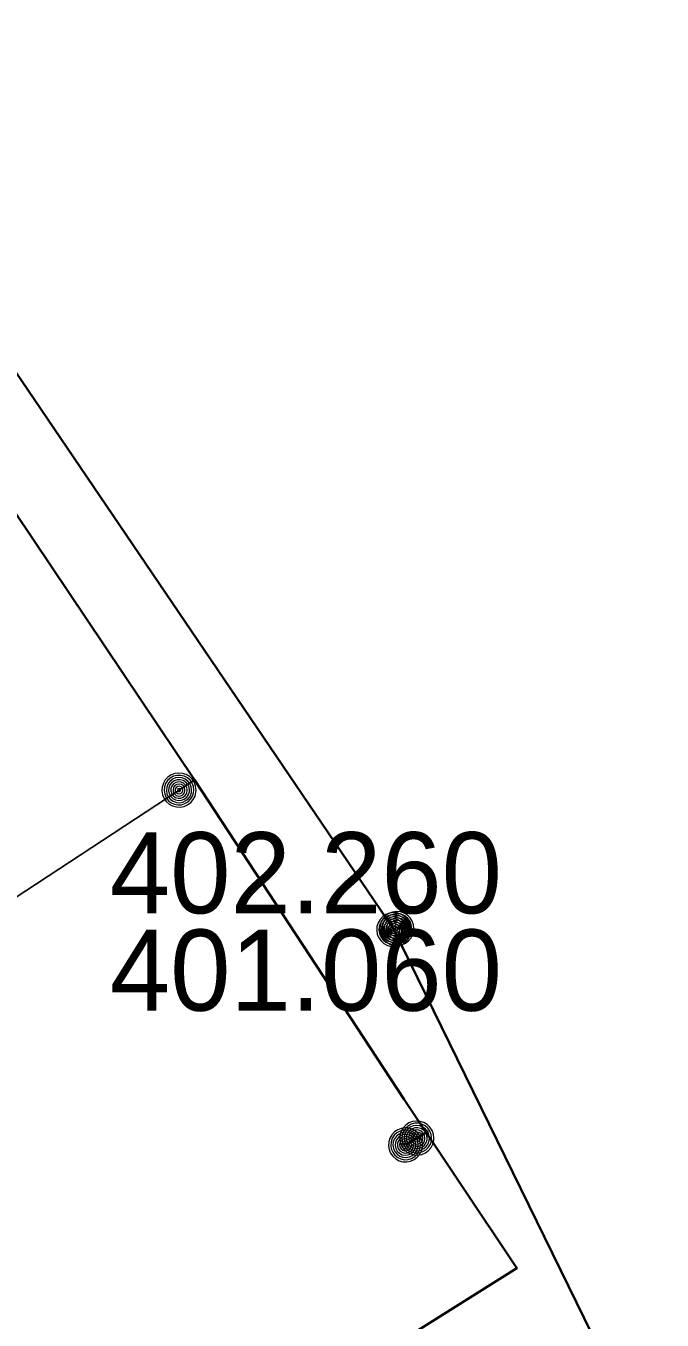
# Model space of a CAD drawing. Extents: x -873619 to -867639, y -1015082 to -1012326.
# Drawn here: x -867894.84 to -867886.21, y -1012917.41 to -1012899.86 of the extents above; entities that cross this region are included whole.
import ezdxf

# ---------------------------------------------------------------- set-up
doc = ezdxf.new("R2010")
doc.units = 0
doc.header["$LTSCALE"] = 0.44
for name, color, linetype, lineweight in [('1', 7, 'Continuous', 13), ('12', 7, 'Continuous', 13), ('21', 7, 'Continuous', 35), ('25', 7, 'Continuous', 13), ('3', 7, 'Continuous', 25), ('32', 7, 'Continuous', 13), ('8', 7, 'Continuous', 13)]:
    doc.layers.add(name, color=color, linetype=linetype, lineweight=lineweight)

msp = doc.modelspace()

# ---------------------------------------------------------------- linework, layer by layer
at = {"layer": '1', "lineweight": 35}
msp.add_line((-867889.689, -1012915.029), (-867889.411, -1012914.86), dxfattribs=at)
msp.add_lwpolyline([(-867979.181, -1012799.683), (-867972.83, -1012801.89), (-867965.59, -1012804.78), (-867963.787, -1012807.409), (-867948.768, -1012827.087), (-867948.538, -1012827.407), (-867943.513, -1012834.828), (-867938.476, -1012842.701), (-867934.013, -1012848.778), (-867931.689, -1012852.506), (-867924.702, -1012862.569), (-867923.496, -1012864.901), (-867916.531, -1012874.592), (-867908.231, -1012887.091), (-867905.717, -1012890.99), (-867899.122, -1012900.29), (-867892.55, -1012910.082), (-867889.71, -1012914.412), (-867888.18, -1012916.7), (-867891.84, -1012919), (-867886.89, -1012927.31), (-867886.728, -1012931.158)], dxfattribs=at)
at = {"layer": '12'}
for points in [[(-867892.53, -1012910.219), (-867892.536, -1012910.167), (-867892.553, -1012910.117), (-867892.582, -1012910.073), (-867892.619, -1012910.036), (-867892.664, -1012910.009), (-867892.714, -1012909.992), (-867892.767, -1012909.988), (-867892.819, -1012909.995), (-867892.868, -1012910.014), (-867892.911, -1012910.043), (-867892.947, -1012910.082), (-867892.973, -1012910.127), (-867892.989, -1012910.178), (-867892.992, -1012910.23), (-867892.984, -1012910.282), (-867892.964, -1012910.331), (-867892.933, -1012910.374), (-867892.894, -1012910.408), (-867892.848, -1012910.434), (-867892.797, -1012910.448), (-867892.744, -1012910.45), (-867892.693, -1012910.44), (-867892.645, -1012910.419), (-867892.602, -1012910.388), (-867892.568, -1012910.347), (-867892.544, -1012910.301), (-867892.532, -1012910.25)], [(-867892.56, -1012910.219), (-867892.566, -1012910.17), (-867892.583, -1012910.124), (-867892.611, -1012910.084), (-867892.648, -1012910.052), (-867892.692, -1012910.03), (-867892.74, -1012910.019), (-867892.789, -1012910.019), (-867892.836, -1012910.032), (-867892.879, -1012910.056), (-867892.915, -1012910.089), (-867892.942, -1012910.13), (-867892.958, -1012910.177), (-867892.962, -1012910.226), (-867892.955, -1012910.274), (-867892.936, -1012910.319), (-867892.906, -1012910.359), (-867892.868, -1012910.39), (-867892.824, -1012910.41), (-867892.776, -1012910.42), (-867892.727, -1012910.418), (-867892.68, -1012910.403), (-867892.637, -1012910.378), (-867892.603, -1012910.344), (-867892.577, -1012910.302), (-867892.563, -1012910.255)], [(-867892.59, -1012910.219), (-867892.596, -1012910.174), (-867892.613, -1012910.132), (-867892.641, -1012910.097), (-867892.677, -1012910.07), (-867892.719, -1012910.053), (-867892.764, -1012910.048), (-867892.809, -1012910.054), (-867892.85, -1012910.073), (-867892.885, -1012910.101), (-867892.912, -1012910.138), (-867892.928, -1012910.18), (-867892.932, -1012910.225), (-867892.925, -1012910.27), (-867892.906, -1012910.311), (-867892.877, -1012910.345), (-867892.84, -1012910.371), (-867892.797, -1012910.387), (-867892.752, -1012910.39), (-867892.707, -1012910.382), (-867892.667, -1012910.362), (-867892.633, -1012910.333), (-867892.607, -1012910.295), (-867892.593, -1012910.252)], [(-867892.62, -1012910.219), (-867892.625, -1012910.178), (-867892.643, -1012910.141), (-867892.67, -1012910.11), (-867892.705, -1012910.089), (-867892.745, -1012910.078), (-867892.786, -1012910.08), (-867892.825, -1012910.093), (-867892.859, -1012910.117), (-867892.884, -1012910.149), (-867892.899, -1012910.187), (-867892.902, -1012910.228), (-867892.894, -1012910.268), (-867892.874, -1012910.304), (-867892.845, -1012910.333), (-867892.808, -1012910.352), (-867892.768, -1012910.36), (-867892.727, -1012910.356), (-867892.689, -1012910.341), (-867892.657, -1012910.315), (-867892.634, -1012910.281), (-867892.621, -1012910.242)], [(-867892.65, -1012910.219), (-867892.655, -1012910.183), (-867892.673, -1012910.151), (-867892.699, -1012910.126), (-867892.733, -1012910.111), (-867892.769, -1012910.108), (-867892.804, -1012910.116), (-867892.835, -1012910.136), (-867892.858, -1012910.164), (-867892.871, -1012910.198), (-867892.871, -1012910.235), (-867892.86, -1012910.27), (-867892.839, -1012910.299), (-867892.809, -1012910.32), (-867892.774, -1012910.33), (-867892.737, -1012910.328), (-867892.703, -1012910.314), (-867892.676, -1012910.291), (-867892.657, -1012910.259), (-867892.65, -1012910.224)], [(-867892.68, -1012910.219), (-867892.685, -1012910.188), (-867892.702, -1012910.162), (-867892.728, -1012910.145), (-867892.758, -1012910.138), (-867892.789, -1012910.142), (-867892.816, -1012910.159), (-867892.834, -1012910.183), (-867892.842, -1012910.214), (-867892.838, -1012910.244), (-867892.823, -1012910.272), (-867892.799, -1012910.291), (-867892.769, -1012910.3), (-867892.738, -1012910.297), (-867892.71, -1012910.283), (-867892.69, -1012910.259), (-867892.68, -1012910.23)], [(-867892.71, -1012910.219), (-867892.715, -1012910.195), (-867892.732, -1012910.177), (-867892.755, -1012910.168), (-867892.779, -1012910.171), (-867892.8, -1012910.185), (-867892.811, -1012910.207), (-867892.811, -1012910.232), (-867892.799, -1012910.253), (-867892.779, -1012910.267), (-867892.754, -1012910.27), (-867892.731, -1012910.261), (-867892.715, -1012910.243)], [(-867892.74, -1012910.219), (-867892.745, -1012910.204), (-867892.76, -1012910.198), (-867892.775, -1012910.202), (-867892.782, -1012910.216), (-867892.778, -1012910.231), (-867892.765, -1012910.24), (-867892.75, -1012910.237), (-867892.74, -1012910.225)], [(-867889.306, -1012914.937), (-867889.312, -1012914.885), (-867889.329, -1012914.835), (-867889.358, -1012914.791), (-867889.395, -1012914.754), (-867889.44, -1012914.727), (-867889.49, -1012914.71), (-867889.543, -1012914.706), (-867889.595, -1012914.713), (-867889.644, -1012914.732), (-867889.687, -1012914.761), (-867889.723, -1012914.8), (-867889.749, -1012914.845), (-867889.765, -1012914.896), (-867889.768, -1012914.948), (-867889.76, -1012915), (-867889.74, -1012915.049), (-867889.709, -1012915.092), (-867889.67, -1012915.126), (-867889.624, -1012915.152), (-867889.573, -1012915.166), (-867889.52, -1012915.168), (-867889.469, -1012915.158), (-867889.421, -1012915.137), (-867889.378, -1012915.106), (-867889.344, -1012915.065), (-867889.32, -1012915.019), (-867889.308, -1012914.968)], [(-867889.336, -1012914.937), (-867889.342, -1012914.888), (-867889.359, -1012914.842), (-867889.387, -1012914.802), (-867889.424, -1012914.77), (-867889.468, -1012914.748), (-867889.516, -1012914.737), (-867889.565, -1012914.737), (-867889.612, -1012914.75), (-867889.655, -1012914.774), (-867889.691, -1012914.807), (-867889.718, -1012914.848), (-867889.734, -1012914.895), (-867889.738, -1012914.944), (-867889.731, -1012914.992), (-867889.712, -1012915.037), (-867889.682, -1012915.077), (-867889.644, -1012915.108), (-867889.6, -1012915.128), (-867889.552, -1012915.138), (-867889.503, -1012915.136), (-867889.456, -1012915.121), (-867889.413, -1012915.096), (-867889.379, -1012915.062), (-867889.353, -1012915.02), (-867889.339, -1012914.973)], [(-867889.366, -1012914.937), (-867889.372, -1012914.892), (-867889.389, -1012914.85), (-867889.417, -1012914.815), (-867889.453, -1012914.788), (-867889.495, -1012914.771), (-867889.54, -1012914.766), (-867889.585, -1012914.772), (-867889.626, -1012914.791), (-867889.661, -1012914.819), (-867889.688, -1012914.856), (-867889.704, -1012914.898), (-867889.708, -1012914.943), (-867889.701, -1012914.988), (-867889.682, -1012915.029), (-867889.653, -1012915.063), (-867889.616, -1012915.089), (-867889.573, -1012915.105), (-867889.528, -1012915.108), (-867889.483, -1012915.1), (-867889.443, -1012915.08), (-867889.409, -1012915.051), (-867889.383, -1012915.013), (-867889.369, -1012914.97)], [(-867889.396, -1012914.937), (-867889.401, -1012914.896), (-867889.419, -1012914.859), (-867889.446, -1012914.828), (-867889.481, -1012914.807), (-867889.521, -1012914.796), (-867889.562, -1012914.798), (-867889.601, -1012914.811), (-867889.635, -1012914.835), (-867889.66, -1012914.867), (-867889.675, -1012914.905), (-867889.678, -1012914.946), (-867889.67, -1012914.986), (-867889.65, -1012915.022), (-867889.621, -1012915.051), (-867889.584, -1012915.07), (-867889.544, -1012915.078), (-867889.503, -1012915.074), (-867889.465, -1012915.059), (-867889.433, -1012915.033), (-867889.41, -1012914.999), (-867889.397, -1012914.96)], [(-867889.426, -1012914.937), (-867889.431, -1012914.901), (-867889.449, -1012914.869), (-867889.475, -1012914.844), (-867889.509, -1012914.829), (-867889.545, -1012914.826), (-867889.58, -1012914.834), (-867889.611, -1012914.854), (-867889.634, -1012914.882), (-867889.647, -1012914.916), (-867889.647, -1012914.953), (-867889.636, -1012914.988), (-867889.615, -1012915.017), (-867889.585, -1012915.038), (-867889.55, -1012915.048), (-867889.513, -1012915.046), (-867889.479, -1012915.032), (-867889.452, -1012915.009), (-867889.433, -1012914.977), (-867889.426, -1012914.942)], [(-867889.456, -1012914.937), (-867889.461, -1012914.906), (-867889.478, -1012914.88), (-867889.504, -1012914.863), (-867889.534, -1012914.856), (-867889.565, -1012914.86), (-867889.592, -1012914.877), (-867889.61, -1012914.901), (-867889.618, -1012914.932), (-867889.614, -1012914.962), (-867889.599, -1012914.99), (-867889.575, -1012915.009), (-867889.545, -1012915.018), (-867889.514, -1012915.015), (-867889.486, -1012915.001), (-867889.466, -1012914.977), (-867889.456, -1012914.948)], [(-867889.486, -1012914.937), (-867889.491, -1012914.913), (-867889.508, -1012914.895), (-867889.531, -1012914.886), (-867889.555, -1012914.889), (-867889.576, -1012914.903), (-867889.587, -1012914.925), (-867889.587, -1012914.95), (-867889.575, -1012914.971), (-867889.555, -1012914.985), (-867889.53, -1012914.988), (-867889.507, -1012914.979), (-867889.491, -1012914.961)], [(-867889.516, -1012914.937), (-867889.521, -1012914.922), (-867889.536, -1012914.916), (-867889.551, -1012914.92), (-867889.558, -1012914.934), (-867889.554, -1012914.949), (-867889.541, -1012914.958), (-867889.526, -1012914.955), (-867889.516, -1012914.943)]]:
    msp.add_lwpolyline(points, close=True, dxfattribs=at)
at = {"layer": '21'}
for p, q in [((-867915.29, -1012874.6), (-867889.85, -1012912.11)), ((-867889.85, -1012912.11), (-867878.653, -1012934.952))]:
    msp.add_line(p, q, dxfattribs=at)
at = {"layer": '25'}
for points in [[(-867889.576, -1012912.096), (-867889.582, -1012912.044), (-867889.599, -1012911.994), (-867889.628, -1012911.95), (-867889.665, -1012911.913), (-867889.71, -1012911.886), (-867889.76, -1012911.869), (-867889.813, -1012911.865), (-867889.865, -1012911.872), (-867889.914, -1012911.891), (-867889.957, -1012911.92), (-867889.993, -1012911.959), (-867890.019, -1012912.004), (-867890.035, -1012912.055), (-867890.038, -1012912.107), (-867890.03, -1012912.159), (-867890.01, -1012912.208), (-867889.979, -1012912.251), (-867889.94, -1012912.285), (-867889.894, -1012912.311), (-867889.843, -1012912.325), (-867889.79, -1012912.327), (-867889.739, -1012912.317), (-867889.691, -1012912.296), (-867889.648, -1012912.265), (-867889.614, -1012912.224), (-867889.59, -1012912.178), (-867889.578, -1012912.127)], [(-867889.606, -1012912.096), (-867889.612, -1012912.047), (-867889.629, -1012912.001), (-867889.657, -1012911.961), (-867889.694, -1012911.929), (-867889.738, -1012911.907), (-867889.786, -1012911.896), (-867889.835, -1012911.896), (-867889.882, -1012911.909), (-867889.925, -1012911.933), (-867889.961, -1012911.966), (-867889.988, -1012912.007), (-867890.004, -1012912.054), (-867890.008, -1012912.103), (-867890.001, -1012912.151), (-867889.982, -1012912.196), (-867889.952, -1012912.236), (-867889.914, -1012912.267), (-867889.87, -1012912.287), (-867889.822, -1012912.297), (-867889.773, -1012912.295), (-867889.726, -1012912.28), (-867889.683, -1012912.255), (-867889.649, -1012912.221), (-867889.623, -1012912.179), (-867889.609, -1012912.132)], [(-867889.636, -1012912.096), (-867889.642, -1012912.051), (-867889.659, -1012912.009), (-867889.687, -1012911.974), (-867889.723, -1012911.947), (-867889.765, -1012911.93), (-867889.81, -1012911.925), (-867889.855, -1012911.931), (-867889.896, -1012911.95), (-867889.931, -1012911.978), (-867889.958, -1012912.015), (-867889.974, -1012912.057), (-867889.978, -1012912.102), (-867889.971, -1012912.147), (-867889.952, -1012912.188), (-867889.923, -1012912.222), (-867889.886, -1012912.248), (-867889.843, -1012912.264), (-867889.798, -1012912.267), (-867889.753, -1012912.259), (-867889.713, -1012912.239), (-867889.679, -1012912.21), (-867889.653, -1012912.172), (-867889.639, -1012912.129)], [(-867889.666, -1012912.096), (-867889.671, -1012912.055), (-867889.689, -1012912.018), (-867889.716, -1012911.987), (-867889.751, -1012911.966), (-867889.791, -1012911.955), (-867889.832, -1012911.957), (-867889.871, -1012911.97), (-867889.905, -1012911.994), (-867889.93, -1012912.026), (-867889.945, -1012912.064), (-867889.948, -1012912.105), (-867889.94, -1012912.145), (-867889.92, -1012912.181), (-867889.891, -1012912.21), (-867889.854, -1012912.229), (-867889.814, -1012912.237), (-867889.773, -1012912.233), (-867889.735, -1012912.218), (-867889.703, -1012912.192), (-867889.68, -1012912.158), (-867889.667, -1012912.119)], [(-867889.696, -1012912.096), (-867889.701, -1012912.06), (-867889.719, -1012912.028), (-867889.745, -1012912.003), (-867889.779, -1012911.988), (-867889.815, -1012911.985), (-867889.85, -1012911.993), (-867889.881, -1012912.013), (-867889.904, -1012912.041), (-867889.917, -1012912.075), (-867889.917, -1012912.112), (-867889.906, -1012912.147), (-867889.885, -1012912.176), (-867889.855, -1012912.197), (-867889.82, -1012912.207), (-867889.783, -1012912.205), (-867889.749, -1012912.191), (-867889.722, -1012912.168), (-867889.703, -1012912.136), (-867889.696, -1012912.101)], [(-867889.726, -1012912.096), (-867889.731, -1012912.065), (-867889.748, -1012912.039), (-867889.774, -1012912.022), (-867889.804, -1012912.015), (-867889.835, -1012912.019), (-867889.862, -1012912.036), (-867889.88, -1012912.06), (-867889.888, -1012912.091), (-867889.884, -1012912.121), (-867889.869, -1012912.149), (-867889.845, -1012912.168), (-867889.815, -1012912.177), (-867889.784, -1012912.174), (-867889.756, -1012912.16), (-867889.736, -1012912.136), (-867889.726, -1012912.107)], [(-867889.756, -1012912.096), (-867889.761, -1012912.072), (-867889.778, -1012912.054), (-867889.801, -1012912.045), (-867889.825, -1012912.048), (-867889.846, -1012912.062), (-867889.857, -1012912.084), (-867889.857, -1012912.109), (-867889.845, -1012912.13), (-867889.825, -1012912.144), (-867889.8, -1012912.147), (-867889.777, -1012912.138), (-867889.761, -1012912.12)], [(-867889.786, -1012912.096), (-867889.791, -1012912.081), (-867889.806, -1012912.075), (-867889.821, -1012912.079), (-867889.828, -1012912.093), (-867889.824, -1012912.108), (-867889.811, -1012912.117), (-867889.796, -1012912.114), (-867889.786, -1012912.102)]]:
    msp.add_lwpolyline(points, close=True, dxfattribs=at)
at = {"layer": '3'}
msp.add_lwpolyline([(-867897.514, -1012913.339), (-867892.759, -1012910.22), (-867892.55, -1012910.082)], dxfattribs=at)
at = {"layer": '32'}
for points in [[(-867889.618, -1012912.11), (-867889.624, -1012912.058), (-867889.641, -1012912.008), (-867889.67, -1012911.964), (-867889.707, -1012911.927), (-867889.752, -1012911.9), (-867889.802, -1012911.883), (-867889.855, -1012911.879), (-867889.907, -1012911.886), (-867889.956, -1012911.905), (-867889.999, -1012911.934), (-867890.035, -1012911.973), (-867890.061, -1012912.018), (-867890.077, -1012912.069), (-867890.08, -1012912.121), (-867890.072, -1012912.173), (-867890.052, -1012912.222), (-867890.021, -1012912.265), (-867889.982, -1012912.299), (-867889.936, -1012912.325), (-867889.885, -1012912.339), (-867889.832, -1012912.341), (-867889.781, -1012912.331), (-867889.733, -1012912.31), (-867889.69, -1012912.279), (-867889.656, -1012912.238), (-867889.632, -1012912.192), (-867889.62, -1012912.141)], [(-867889.648, -1012912.11), (-867889.654, -1012912.061), (-867889.671, -1012912.015), (-867889.699, -1012911.975), (-867889.736, -1012911.943), (-867889.78, -1012911.921), (-867889.828, -1012911.91), (-867889.877, -1012911.91), (-867889.924, -1012911.923), (-867889.967, -1012911.947), (-867890.003, -1012911.98), (-867890.03, -1012912.021), (-867890.046, -1012912.068), (-867890.05, -1012912.117), (-867890.043, -1012912.165), (-867890.024, -1012912.21), (-867889.994, -1012912.25), (-867889.956, -1012912.281), (-867889.912, -1012912.301), (-867889.864, -1012912.311), (-867889.815, -1012912.309), (-867889.768, -1012912.294), (-867889.725, -1012912.269), (-867889.691, -1012912.235), (-867889.665, -1012912.193), (-867889.651, -1012912.146)], [(-867889.678, -1012912.11), (-867889.684, -1012912.065), (-867889.701, -1012912.023), (-867889.729, -1012911.988), (-867889.765, -1012911.961), (-867889.807, -1012911.944), (-867889.852, -1012911.939), (-867889.897, -1012911.945), (-867889.938, -1012911.964), (-867889.973, -1012911.992), (-867890, -1012912.029), (-867890.016, -1012912.071), (-867890.02, -1012912.116), (-867890.013, -1012912.161), (-867889.994, -1012912.202), (-867889.965, -1012912.236), (-867889.928, -1012912.262), (-867889.885, -1012912.278), (-867889.84, -1012912.281), (-867889.795, -1012912.273), (-867889.755, -1012912.253), (-867889.721, -1012912.224), (-867889.695, -1012912.186), (-867889.681, -1012912.143)], [(-867889.708, -1012912.11), (-867889.713, -1012912.069), (-867889.731, -1012912.032), (-867889.758, -1012912.001), (-867889.793, -1012911.98), (-867889.833, -1012911.969), (-867889.874, -1012911.971), (-867889.913, -1012911.984), (-867889.947, -1012912.008), (-867889.972, -1012912.04), (-867889.987, -1012912.078), (-867889.99, -1012912.119), (-867889.982, -1012912.159), (-867889.962, -1012912.195), (-867889.933, -1012912.224), (-867889.896, -1012912.243), (-867889.856, -1012912.251), (-867889.815, -1012912.247), (-867889.777, -1012912.232), (-867889.745, -1012912.206), (-867889.722, -1012912.172), (-867889.709, -1012912.133)], [(-867889.738, -1012912.11), (-867889.743, -1012912.074), (-867889.761, -1012912.042), (-867889.787, -1012912.017), (-867889.821, -1012912.002), (-867889.857, -1012911.999), (-867889.892, -1012912.007), (-867889.923, -1012912.027), (-867889.946, -1012912.055), (-867889.959, -1012912.089), (-867889.959, -1012912.126), (-867889.948, -1012912.161), (-867889.927, -1012912.19), (-867889.897, -1012912.211), (-867889.862, -1012912.221), (-867889.825, -1012912.219), (-867889.791, -1012912.205), (-867889.764, -1012912.182), (-867889.745, -1012912.15), (-867889.738, -1012912.115)], [(-867889.768, -1012912.11), (-867889.773, -1012912.079), (-867889.79, -1012912.053), (-867889.816, -1012912.036), (-867889.846, -1012912.029), (-867889.877, -1012912.033), (-867889.904, -1012912.05), (-867889.922, -1012912.074), (-867889.93, -1012912.105), (-867889.926, -1012912.135), (-867889.911, -1012912.163), (-867889.887, -1012912.182), (-867889.857, -1012912.191), (-867889.826, -1012912.188), (-867889.798, -1012912.174), (-867889.778, -1012912.15), (-867889.768, -1012912.121)], [(-867889.798, -1012912.11), (-867889.803, -1012912.086), (-867889.82, -1012912.068), (-867889.843, -1012912.059), (-867889.867, -1012912.062), (-867889.888, -1012912.076), (-867889.899, -1012912.098), (-867889.899, -1012912.123), (-867889.887, -1012912.144), (-867889.867, -1012912.158), (-867889.842, -1012912.161), (-867889.819, -1012912.152), (-867889.803, -1012912.134)], [(-867889.828, -1012912.11), (-867889.833, -1012912.095), (-867889.848, -1012912.089), (-867889.863, -1012912.093), (-867889.87, -1012912.107), (-867889.866, -1012912.122), (-867889.853, -1012912.131), (-867889.838, -1012912.128), (-867889.828, -1012912.116)]]:
    msp.add_lwpolyline(points, close=True, dxfattribs=at)
at = {"layer": '8'}
for points in [[(-867889.458, -1012915.029), (-867889.464, -1012914.977), (-867889.481, -1012914.927), (-867889.51, -1012914.883), (-867889.547, -1012914.846), (-867889.592, -1012914.819), (-867889.642, -1012914.802), (-867889.695, -1012914.798), (-867889.747, -1012914.805), (-867889.796, -1012914.824), (-867889.839, -1012914.853), (-867889.875, -1012914.892), (-867889.901, -1012914.937), (-867889.917, -1012914.988), (-867889.92, -1012915.04), (-867889.912, -1012915.092), (-867889.892, -1012915.141), (-867889.861, -1012915.184), (-867889.822, -1012915.218), (-867889.776, -1012915.244), (-867889.725, -1012915.258), (-867889.672, -1012915.26), (-867889.621, -1012915.25), (-867889.573, -1012915.229), (-867889.53, -1012915.198), (-867889.496, -1012915.157), (-867889.472, -1012915.111), (-867889.46, -1012915.06)], [(-867889.488, -1012915.029), (-867889.494, -1012914.98), (-867889.511, -1012914.934), (-867889.539, -1012914.894), (-867889.576, -1012914.862), (-867889.62, -1012914.84), (-867889.668, -1012914.829), (-867889.717, -1012914.829), (-867889.764, -1012914.842), (-867889.807, -1012914.866), (-867889.843, -1012914.899), (-867889.87, -1012914.94), (-867889.886, -1012914.987), (-867889.89, -1012915.036), (-867889.883, -1012915.084), (-867889.864, -1012915.129), (-867889.834, -1012915.169), (-867889.796, -1012915.2), (-867889.752, -1012915.22), (-867889.704, -1012915.23), (-867889.655, -1012915.228), (-867889.608, -1012915.213), (-867889.565, -1012915.188), (-867889.531, -1012915.154), (-867889.505, -1012915.112), (-867889.491, -1012915.065)], [(-867889.518, -1012915.029), (-867889.524, -1012914.984), (-867889.541, -1012914.942), (-867889.569, -1012914.907), (-867889.605, -1012914.88), (-867889.647, -1012914.863), (-867889.692, -1012914.858), (-867889.737, -1012914.864), (-867889.778, -1012914.883), (-867889.813, -1012914.911), (-867889.84, -1012914.948), (-867889.856, -1012914.99), (-867889.86, -1012915.035), (-867889.853, -1012915.08), (-867889.834, -1012915.121), (-867889.805, -1012915.155), (-867889.768, -1012915.181), (-867889.725, -1012915.197), (-867889.68, -1012915.2), (-867889.635, -1012915.192), (-867889.595, -1012915.172), (-867889.561, -1012915.143), (-867889.535, -1012915.105), (-867889.521, -1012915.062)], [(-867889.548, -1012915.029), (-867889.553, -1012914.988), (-867889.571, -1012914.951), (-867889.598, -1012914.92), (-867889.633, -1012914.899), (-867889.673, -1012914.888), (-867889.714, -1012914.89), (-867889.753, -1012914.903), (-867889.787, -1012914.927), (-867889.812, -1012914.959), (-867889.827, -1012914.997), (-867889.83, -1012915.038), (-867889.822, -1012915.078), (-867889.802, -1012915.114), (-867889.773, -1012915.143), (-867889.736, -1012915.162), (-867889.696, -1012915.17), (-867889.655, -1012915.166), (-867889.617, -1012915.151), (-867889.585, -1012915.125), (-867889.562, -1012915.091), (-867889.549, -1012915.052)], [(-867889.578, -1012915.029), (-867889.583, -1012914.993), (-867889.601, -1012914.961), (-867889.627, -1012914.936), (-867889.661, -1012914.921), (-867889.697, -1012914.918), (-867889.732, -1012914.926), (-867889.763, -1012914.946), (-867889.786, -1012914.974), (-867889.799, -1012915.008), (-867889.799, -1012915.045), (-867889.788, -1012915.08), (-867889.767, -1012915.109), (-867889.737, -1012915.13), (-867889.702, -1012915.14), (-867889.665, -1012915.138), (-867889.631, -1012915.124), (-867889.604, -1012915.101), (-867889.585, -1012915.069), (-867889.578, -1012915.034)], [(-867889.608, -1012915.029), (-867889.613, -1012914.998), (-867889.63, -1012914.972), (-867889.656, -1012914.955), (-867889.686, -1012914.948), (-867889.717, -1012914.952), (-867889.744, -1012914.969), (-867889.762, -1012914.993), (-867889.77, -1012915.024), (-867889.766, -1012915.054), (-867889.751, -1012915.082), (-867889.727, -1012915.101), (-867889.697, -1012915.11), (-867889.666, -1012915.107), (-867889.638, -1012915.093), (-867889.618, -1012915.069), (-867889.608, -1012915.04)], [(-867889.638, -1012915.029), (-867889.643, -1012915.005), (-867889.66, -1012914.987), (-867889.683, -1012914.978), (-867889.707, -1012914.981), (-867889.728, -1012914.995), (-867889.739, -1012915.017), (-867889.739, -1012915.042), (-867889.727, -1012915.063), (-867889.707, -1012915.077), (-867889.682, -1012915.08), (-867889.659, -1012915.071), (-867889.643, -1012915.053)], [(-867889.668, -1012915.029), (-867889.673, -1012915.014), (-867889.688, -1012915.008), (-867889.703, -1012915.012), (-867889.71, -1012915.026), (-867889.706, -1012915.041), (-867889.693, -1012915.05), (-867889.678, -1012915.047), (-867889.668, -1012915.035)]]:
    msp.add_lwpolyline(points, close=True, dxfattribs=at)

# ---------------------------------------------------------------- texts
at = {"layer": '1'}
for s, p in [('402.260 ', (-867893.699, -1012911.89)), ('401.060 ', (-867893.699, -1012913.21))]:
    msp.add_text(s, height=1.1, dxfattribs=at).set_placement(p)

doc.saveas('drawing.dxf')
